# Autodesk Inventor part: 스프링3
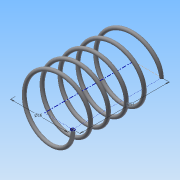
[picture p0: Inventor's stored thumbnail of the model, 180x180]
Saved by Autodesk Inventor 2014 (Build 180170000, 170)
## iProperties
Created: 2015-06
Part Number: 스프링3
Material: 강철, 연강
Document SubType Name: Modeling
Designer: Administrator
Density: 7.86 g/cm^3
Appearance: 강철
Mass: 1.53535 g
Surface Area: 7.89042 cm^2
Volume: 0.195337 cm^3
Author: Administrator
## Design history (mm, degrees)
sketch "스케치1"
  geometry: L1 (0, 0)-(8, 0); L2 (8, 0)-(8, 21.5); L3 (8, 21.5)-(0, 21.5); L4 (0, 21.5)-(0, 0); C1 r 0.5 at (8, 0)
  constraints: 8 end point, 2 parallel, 1 centre point, 1 coincident, 1 horizontal, 1 perpendicular
  dimensions: "d1" = 1 diameter of C1; "d2" = 16 diameter of L2 L4; "d3" = 21.5 distance of L1.end L2.end (derived)
feature "코일1" sketch "스케치1" pitch "d4" = 10; turns "d6" = 5; dims "d5" = 21.5 (= d3), "d7" = 0, angle "d8" = 90 deg, angle "d9" = 90 deg, "d10" = 0, "d11" = 0
sketch "스케치2"
  geometry: L1 (-8.5, 0)-(-7.5, 0) reference; 1 further point
  constraints: 1 horizontal alignment
extrude "돌출1" cut sketch "스케치2" stored distance "d12" = 10; taper "d13" = 0 deg
node "작업 평면1"
sketch "스케치3"
  geometry: L1 (8.5, 0)-(7.5, 0) reference; 1 further point
  constraints: 1 horizontal alignment
extrude "돌출2" cut sketch "스케치3" stored distance "d15" = 10; taper "d16" = 0 deg
node "솔리드1"
node "절단 모서리 투영1"
node "절단 모서리 투영2"
other parameters: "d14" = -21.5 (= -d3)
